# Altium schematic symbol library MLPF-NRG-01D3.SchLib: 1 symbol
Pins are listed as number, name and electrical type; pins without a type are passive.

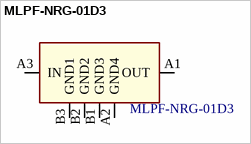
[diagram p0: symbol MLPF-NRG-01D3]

## MLPF-NRG-01D3
designator U?
footprint ST_CSP6N50P2x3_160x100x63
pins: A1 OUT, A2 GND4, A3 IN, B1 GND3, B2 GND2, B3 GND1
